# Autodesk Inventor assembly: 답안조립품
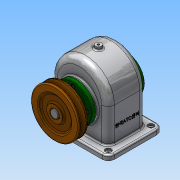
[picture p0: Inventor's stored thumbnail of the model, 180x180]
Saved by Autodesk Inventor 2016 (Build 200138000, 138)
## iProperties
Created: 2018-08
Part Number: 답안조립품
Material: 일반
Document SubType Name: Assembly
Designer: Administrator
Author: Administrator
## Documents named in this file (13)
- C:\Users\Administrator\Desktop\480811V1016\답안조립품.iam
- C:\Users\Administrator\Desktop\480811V1016\본체.ipt
- C:\Users\Administrator\Desktop\480811V1016\축.ipt
- C:\Users\Administrator\Desktop\480811V1016\키 6x6x22.ipt
- C:\Users\Administrator\Desktop\480811V1016\베어링 6203.ipt
- C:\Users\Administrator\Desktop\480811V1016\스퍼기어.ipt
- C:\Users\Administrator\Desktop\480811V1016\뒤커버.ipt
- C:\Users\Administrator\Desktop\480811V1016\볼트 M4.ipt
- C:\Users\Administrator\Desktop\480811V1016\앞커버.ipt
- C:\Users\Administrator\Desktop\480811V1016\키 5x5x18.ipt
- C:\Users\Administrator\Desktop\480811V1016\오일 실 28 40 8.ipt
- C:\Users\Administrator\Desktop\480811V1016\V-벨트풀리.ipt
- C:\Users\Administrator\Desktop\480811V1016\멈춤나사 M4.ipt
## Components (1 placed, 1 different names)
1. V-벨트풀리:1
